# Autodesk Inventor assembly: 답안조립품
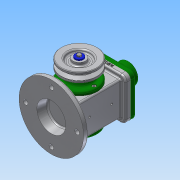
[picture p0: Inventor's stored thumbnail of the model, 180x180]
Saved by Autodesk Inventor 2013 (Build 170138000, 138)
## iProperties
Created: 2018-10
Part Number: 답안조립품
Document SubType Name: Assembly
Designer: Administrator
Author: Administrator
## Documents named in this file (18)
- C:\Users\Administrator\Desktop\481007V1035\답안조립품.iam
- C:\Users\Administrator\Desktop\481007V1035\본체.ipt
- C:\Users\Administrator\Desktop\481007V1035\E-링.ipt
- C:\Users\Administrator\Desktop\481007V1035\V-벨트풀리.ipt
- C:\Users\Administrator\Desktop\481007V1035\덮개.ipt
- C:\Users\Administrator\Desktop\481007V1035\뒤커버.ipt
- C:\Users\Administrator\Desktop\481007V1035\링크.ipt
- C:\Users\Administrator\Desktop\481007V1035\베어링 17 x 40 x 12.ipt
- C:\Users\Administrator\Desktop\481007V1035\볼트 M4 x 8.ipt
- C:\Users\Administrator\Desktop\481007V1035\볼트 M4 x 10.ipt
- C:\Users\Administrator\Desktop\481007V1035\슬라이더.ipt
- C:\Users\Administrator\Desktop\481007V1035\앞커버.ipt
- C:\Users\Administrator\Desktop\481007V1035\오일 실 17 30 8.ipt
- C:\Users\Administrator\Desktop\481007V1035\와셔 4x16.ipt
- C:\Users\Administrator\Desktop\481007V1035\클레비스 핀 6 x 22.ipt
- 클레비스 핀 6 x 22.ipt
- C:\Users\Administrator\Desktop\481007V1035\키 4 x 4 x 12.ipt
- C:\Users\Administrator\Desktop\481007V1035\편심축.ipt
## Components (2 placed, 2 different names)
1. E-링:1
2. V-벨트풀리:1 — 플러쉬:1
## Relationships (1: Flush 1)
- 플러쉬:1 [Flush]: V-벨트풀리:1
